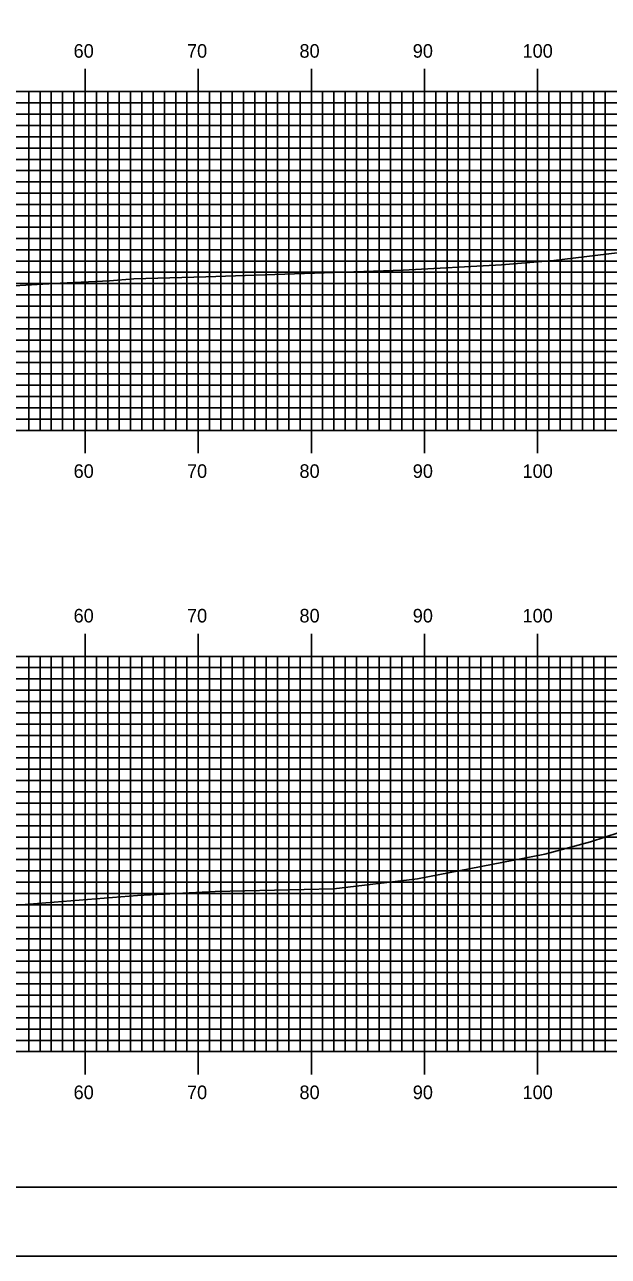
# Model space of a CAD drawing. Extents: x 1763365 to 1763708, y 442591 to 442811.
# Drawn here: x 1763585.5 to 1763637.1, y 442590.5 to 442699.6 of the extents above; entities that cross this region are included whole.
import ezdxf

# ---------------------------------------------------------------- set-up
doc = ezdxf.new("R2010")
doc.units = 0
for name, color, linetype in [('BORDER', 7, 'Continuous'), ('H_V ANNOTATION', 7, 'Continuous'), ('MAJOR', 7, 'Continuous'), ('MINOR', 7, 'Continuous'), ('PLOT BOUNDARY', 7, 'Continuous'), ('S_Roadway_Centerline', 7, 'Continuous')]:
    doc.layers.add(name, color=color, linetype=linetype)

msp = doc.modelspace()

# ---------------------------------------------------------------- linework, layer by layer
at = {"layer": 'BORDER'}
msp.add_lwpolyline([(1763381.21, 442596.67), (1763701.21, 442596.67), (1763701.21, 442806.67), (1763381.21, 442806.67)], close=True, dxfattribs=at)
at = {"layer": 'MAJOR'}
for p, q in [((1763590.81, 442695.67), (1763590.81, 442693.67)), ((1763600.81, 442695.67), (1763600.81, 442693.67)), ((1763610.81, 442695.67), (1763610.81, 442693.67)), ((1763620.81, 442695.67), (1763620.81, 442693.67)), ((1763630.81, 442695.67), (1763630.81, 442693.67)), ((1763390.81, 442693.67), (1763670.81, 442693.67)), ((1763390.81, 442693.67), (1763670.81, 442693.67)), ((1763590.81, 442663.67), (1763590.81, 442693.67)), ((1763600.81, 442663.67), (1763600.81, 442693.67)), ((1763610.81, 442663.67), (1763610.81, 442693.67)), ((1763620.81, 442663.67), (1763620.81, 442693.67)), ((1763630.81, 442663.67), (1763630.81, 442693.67)), ((1763390.81, 442688.67), (1763670.81, 442688.67)), ((1763390.81, 442683.67), (1763670.81, 442683.67)), ((1763390.81, 442678.67), (1763670.81, 442678.67)), ((1763390.81, 442673.67), (1763670.81, 442673.67)), ((1763390.81, 442668.67), (1763670.81, 442668.67)), ((1763390.81, 442663.67), (1763670.81, 442663.67)), ((1763390.81, 442663.67), (1763670.81, 442663.67)), ((1763590.81, 442661.66), (1763590.81, 442663.67)), ((1763600.81, 442661.66), (1763600.81, 442663.67)), ((1763610.81, 442661.66), (1763610.81, 442663.67)), ((1763620.81, 442661.66), (1763620.81, 442663.67)), ((1763630.81, 442661.66), (1763630.81, 442663.67)), ((1763590.81, 442645.67), (1763590.81, 442643.67)), ((1763600.81, 442645.67), (1763600.81, 442643.67)), ((1763610.81, 442645.67), (1763610.81, 442643.67)), ((1763620.81, 442645.67), (1763620.81, 442643.67)), ((1763630.81, 442645.67), (1763630.81, 442643.67)), ((1763390.81, 442643.67), (1763670.81, 442643.67)), ((1763390.81, 442643.67), (1763670.81, 442643.67)), ((1763590.81, 442608.67), (1763590.81, 442643.67)), ((1763600.81, 442608.67), (1763600.81, 442643.67)), ((1763610.81, 442608.67), (1763610.81, 442643.67)), ((1763620.81, 442608.67), (1763620.81, 442643.67)), ((1763630.81, 442608.67), (1763630.81, 442643.67)), ((1763390.81, 442638.67), (1763670.81, 442638.67)), ((1763390.81, 442633.67), (1763670.81, 442633.67)), ((1763390.81, 442628.67), (1763670.81, 442628.67)), ((1763390.81, 442623.67), (1763670.81, 442623.67)), ((1763390.81, 442618.67), (1763670.81, 442618.67)), ((1763390.81, 442613.67), (1763670.81, 442613.67)), ((1763390.81, 442608.67), (1763670.81, 442608.67)), ((1763390.81, 442608.67), (1763670.81, 442608.67)), ((1763590.81, 442606.66), (1763590.81, 442608.67)), ((1763600.81, 442606.66), (1763600.81, 442608.67)), ((1763610.81, 442606.66), (1763610.81, 442608.67)), ((1763620.81, 442606.66), (1763620.81, 442608.67)), ((1763630.81, 442606.66), (1763630.81, 442608.67))]:
    msp.add_line(p, q, dxfattribs=at)
at = {"layer": 'MINOR'}
for p, q in [((1763585.81, 442663.67), (1763585.81, 442693.67)), ((1763586.81, 442663.67), (1763586.81, 442693.67)), ((1763587.81, 442663.67), (1763587.81, 442693.67)), ((1763588.81, 442663.67), (1763588.81, 442693.67)), ((1763589.81, 442663.67), (1763589.81, 442693.67)), ((1763591.81, 442663.67), (1763591.81, 442693.67)), ((1763592.81, 442663.67), (1763592.81, 442693.67)), ((1763593.81, 442663.67), (1763593.81, 442693.67)), ((1763594.81, 442663.67), (1763594.81, 442693.67)), ((1763595.81, 442663.67), (1763595.81, 442693.67)), ((1763596.81, 442663.67), (1763596.81, 442693.67)), ((1763597.81, 442663.67), (1763597.81, 442693.67)), ((1763598.81, 442663.67), (1763598.81, 442693.67)), ((1763599.81, 442663.67), (1763599.81, 442693.67)), ((1763601.81, 442663.67), (1763601.81, 442693.67)), ((1763602.81, 442663.67), (1763602.81, 442693.67)), ((1763603.81, 442663.67), (1763603.81, 442693.67)), ((1763604.81, 442663.67), (1763604.81, 442693.67)), ((1763605.81, 442663.67), (1763605.81, 442693.67)), ((1763606.81, 442663.67), (1763606.81, 442693.67)), ((1763607.81, 442663.67), (1763607.81, 442693.67)), ((1763608.81, 442663.67), (1763608.81, 442693.67)), ((1763609.81, 442663.67), (1763609.81, 442693.67)), ((1763611.81, 442663.67), (1763611.81, 442693.67)), ((1763612.81, 442663.67), (1763612.81, 442693.67)), ((1763613.81, 442663.67), (1763613.81, 442693.67)), ((1763614.81, 442663.67), (1763614.81, 442693.67)), ((1763615.81, 442663.67), (1763615.81, 442693.67)), ((1763616.81, 442663.67), (1763616.81, 442693.67)), ((1763617.81, 442663.67), (1763617.81, 442693.67)), ((1763618.81, 442663.67), (1763618.81, 442693.67)), ((1763619.81, 442663.67), (1763619.81, 442693.67)), ((1763621.81, 442663.67), (1763621.81, 442693.67)), ((1763622.81, 442663.67), (1763622.81, 442693.67)), ((1763623.81, 442663.67), (1763623.81, 442693.67)), ((1763624.81, 442663.67), (1763624.81, 442693.67)), ((1763625.81, 442663.67), (1763625.81, 442693.67)), ((1763626.81, 442663.67), (1763626.81, 442693.67)), ((1763627.81, 442663.67), (1763627.81, 442693.67)), ((1763628.81, 442663.67), (1763628.81, 442693.67)), ((1763629.81, 442663.67), (1763629.81, 442693.67)), ((1763631.81, 442663.67), (1763631.81, 442693.67)), ((1763632.81, 442663.67), (1763632.81, 442693.67)), ((1763633.81, 442663.67), (1763633.81, 442693.67)), ((1763634.81, 442663.67), (1763634.81, 442693.67)), ((1763635.81, 442663.67), (1763635.81, 442693.67)), ((1763636.81, 442663.67), (1763636.81, 442693.67)), ((1763390.81, 442692.67), (1763670.81, 442692.67)), ((1763390.81, 442691.67), (1763670.81, 442691.67)), ((1763390.81, 442690.67), (1763670.81, 442690.67)), ((1763390.81, 442689.67), (1763670.81, 442689.67)), ((1763390.81, 442687.67), (1763670.81, 442687.67)), ((1763390.81, 442686.67), (1763670.81, 442686.67)), ((1763390.81, 442685.67), (1763670.81, 442685.67)), ((1763390.81, 442684.67), (1763670.81, 442684.67)), ((1763390.81, 442682.67), (1763670.81, 442682.67)), ((1763390.81, 442681.67), (1763670.81, 442681.67)), ((1763390.81, 442680.67), (1763670.81, 442680.67)), ((1763390.81, 442679.67), (1763670.81, 442679.67)), ((1763390.81, 442677.67), (1763670.81, 442677.67)), ((1763390.81, 442676.67), (1763670.81, 442676.67)), ((1763390.81, 442675.67), (1763670.81, 442675.67)), ((1763390.81, 442674.67), (1763670.81, 442674.67)), ((1763390.81, 442672.67), (1763670.81, 442672.67)), ((1763390.81, 442671.67), (1763670.81, 442671.67)), ((1763390.81, 442670.67), (1763670.81, 442670.67)), ((1763390.81, 442669.67), (1763670.81, 442669.67)), ((1763390.81, 442667.67), (1763670.81, 442667.67)), ((1763390.81, 442666.67), (1763670.81, 442666.67)), ((1763390.81, 442665.67), (1763670.81, 442665.67)), ((1763390.81, 442664.67), (1763670.81, 442664.67)), ((1763585.81, 442608.67), (1763585.81, 442643.67)), ((1763586.81, 442608.67), (1763586.81, 442643.67)), ((1763587.81, 442608.67), (1763587.81, 442643.67)), ((1763588.81, 442608.67), (1763588.81, 442643.67)), ((1763589.81, 442608.67), (1763589.81, 442643.67)), ((1763591.81, 442608.67), (1763591.81, 442643.67)), ((1763592.81, 442608.67), (1763592.81, 442643.67)), ((1763593.81, 442608.67), (1763593.81, 442643.67)), ((1763594.81, 442608.67), (1763594.81, 442643.67)), ((1763595.81, 442608.67), (1763595.81, 442643.67)), ((1763596.81, 442608.67), (1763596.81, 442643.67)), ((1763597.81, 442608.67), (1763597.81, 442643.67)), ((1763598.81, 442608.67), (1763598.81, 442643.67)), ((1763599.81, 442608.67), (1763599.81, 442643.67)), ((1763601.81, 442608.67), (1763601.81, 442643.67)), ((1763602.81, 442608.67), (1763602.81, 442643.67)), ((1763603.81, 442608.67), (1763603.81, 442643.67)), ((1763604.81, 442608.67), (1763604.81, 442643.67)), ((1763605.81, 442608.67), (1763605.81, 442643.67)), ((1763606.81, 442608.67), (1763606.81, 442643.67)), ((1763607.81, 442608.67), (1763607.81, 442643.67)), ((1763608.81, 442608.67), (1763608.81, 442643.67)), ((1763609.81, 442608.67), (1763609.81, 442643.67)), ((1763611.81, 442608.67), (1763611.81, 442643.67)), ((1763612.81, 442608.67), (1763612.81, 442643.67)), ((1763613.81, 442608.67), (1763613.81, 442643.67)), ((1763614.81, 442608.67), (1763614.81, 442643.67)), ((1763615.81, 442608.67), (1763615.81, 442643.67)), ((1763616.81, 442608.67), (1763616.81, 442643.67)), ((1763617.81, 442608.67), (1763617.81, 442643.67)), ((1763618.81, 442608.67), (1763618.81, 442643.67)), ((1763619.81, 442608.67), (1763619.81, 442643.67)), ((1763621.81, 442608.67), (1763621.81, 442643.67)), ((1763622.81, 442608.67), (1763622.81, 442643.67)), ((1763623.81, 442608.67), (1763623.81, 442643.67)), ((1763624.81, 442608.67), (1763624.81, 442643.67)), ((1763625.81, 442608.67), (1763625.81, 442643.67)), ((1763626.81, 442608.67), (1763626.81, 442643.67)), ((1763627.81, 442608.67), (1763627.81, 442643.67)), ((1763628.81, 442608.67), (1763628.81, 442643.67)), ((1763629.81, 442608.67), (1763629.81, 442643.67)), ((1763631.81, 442608.67), (1763631.81, 442643.67)), ((1763632.81, 442608.67), (1763632.81, 442643.67)), ((1763633.81, 442608.67), (1763633.81, 442643.67)), ((1763634.81, 442608.67), (1763634.81, 442643.67)), ((1763635.81, 442608.67), (1763635.81, 442643.67)), ((1763636.81, 442608.67), (1763636.81, 442643.67)), ((1763390.81, 442642.67), (1763670.81, 442642.67)), ((1763390.81, 442641.67), (1763670.81, 442641.67)), ((1763390.81, 442640.67), (1763670.81, 442640.67)), ((1763390.81, 442639.67), (1763670.81, 442639.67)), ((1763390.81, 442637.67), (1763670.81, 442637.67)), ((1763390.81, 442636.67), (1763670.81, 442636.67)), ((1763390.81, 442635.67), (1763670.81, 442635.67)), ((1763390.81, 442634.67), (1763670.81, 442634.67)), ((1763390.81, 442632.67), (1763670.81, 442632.67)), ((1763390.81, 442631.67), (1763670.81, 442631.67)), ((1763390.81, 442630.67), (1763670.81, 442630.67)), ((1763390.81, 442629.67), (1763670.81, 442629.67)), ((1763390.81, 442627.67), (1763670.81, 442627.67)), ((1763390.81, 442626.67), (1763670.81, 442626.67)), ((1763390.81, 442625.67), (1763670.81, 442625.67)), ((1763390.81, 442624.67), (1763670.81, 442624.67)), ((1763390.81, 442622.67), (1763670.81, 442622.67)), ((1763390.81, 442621.67), (1763670.81, 442621.67)), ((1763390.81, 442620.67), (1763670.81, 442620.67)), ((1763390.81, 442619.67), (1763670.81, 442619.67)), ((1763390.81, 442617.67), (1763670.81, 442617.67)), ((1763390.81, 442616.67), (1763670.81, 442616.67)), ((1763390.81, 442615.67), (1763670.81, 442615.67)), ((1763390.81, 442614.67), (1763670.81, 442614.67)), ((1763390.81, 442612.67), (1763670.81, 442612.67)), ((1763390.81, 442611.67), (1763670.81, 442611.67)), ((1763390.81, 442610.67), (1763670.81, 442610.67)), ((1763390.81, 442609.67), (1763670.81, 442609.67))]:
    msp.add_line(p, q, dxfattribs=at)
at = {"layer": 'PLOT BOUNDARY'}
msp.add_lwpolyline([(1763365.02, 442590.55), (1763705.02, 442590.55), (1763705.02, 442810.55), (1763365.02, 442810.55)], close=True, dxfattribs=at)
at = {"layer": 'S_Roadway_Centerline'}
for points in [[(1763581.46, 442676.29), (1763588.6, 442676.71), (1763592.96, 442676.91), (1763595.12, 442677.08), (1763601.47, 442677.26), (1763618.94, 442677.86), (1763627.63, 442678.34), (1763632.26, 442678.72), (1763637.85, 442679.39), (1763649.83, 442680.7), (1763653.8, 442681.08), (1763662.38, 442683.31), (1763666.22, 442684.37), (1763668.01, 442684.87), (1763670.81, 442685.38)], [(1763584.37, 442621.6), (1763595.43, 442622.5), (1763602.3, 442622.86), (1763612.81, 442623.1), (1763620.21, 442623.98), (1763631.45, 442626.15), (1763635.5, 442627.24), (1763638.05, 442628.07), (1763648.67, 442631.5), (1763656.9, 442633.95), (1763668.02, 442636.65), (1763670.81, 442637.18)]]:
    msp.add_lwpolyline(points, dxfattribs=at)

# ---------------------------------------------------------------- texts
at = {"layer": 'H_V ANNOTATION'}
for s, p in [('60', (1763589.78, 442696.67)), ('70', (1763599.81, 442696.67)), ('80', (1763609.76, 442696.67)), ('90', (1763619.78, 442696.67)), ('100', (1763629.49, 442696.67)), ('60', (1763589.78, 442659.47)), ('70', (1763599.81, 442659.47)), ('80', (1763609.76, 442659.47)), ('90', (1763619.78, 442659.47)), ('100', (1763629.49, 442659.47)), ('60', (1763589.78, 442646.67)), ('70', (1763599.81, 442646.67)), ('80', (1763609.76, 442646.67)), ('90', (1763619.78, 442646.67)), ('100', (1763629.49, 442646.67)), ('60', (1763589.78, 442604.47)), ('70', (1763599.81, 442604.47)), ('80', (1763609.76, 442604.47)), ('90', (1763619.78, 442604.47)), ('100', (1763629.49, 442604.47))]:
    msp.add_text(s, height=1.2, dxfattribs=at).set_placement(p)

doc.saveas('drawing.dxf')
